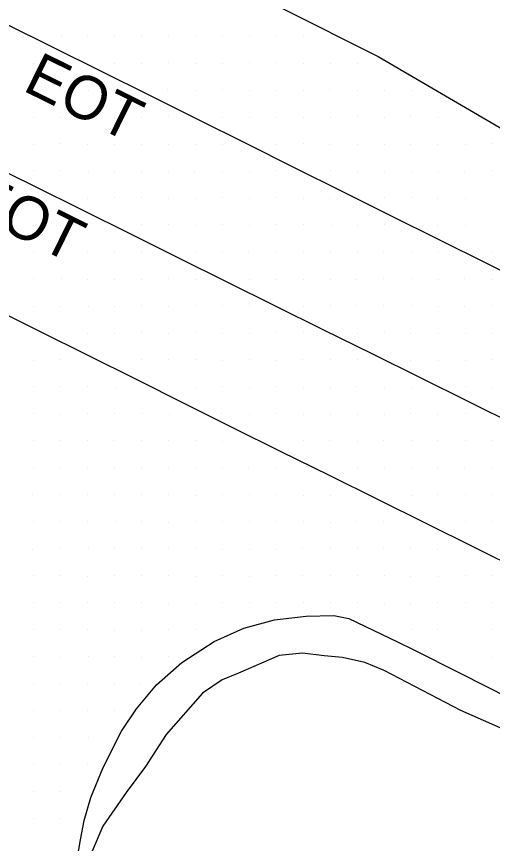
# Model space of a CAD drawing. Extents: x 2244337 to 2251208, y 199469 to 202984.
# Drawn here: x 2248960 to 2249004.1, y 200612.9 to 200689.5 of the extents above; entities that cross this region are included whole.
import ezdxf

# ---------------------------------------------------------------- set-up
doc = ezdxf.new("R2010")
doc.units = 0
for name, color, linetype in [('Exist DTM Scan Elevation Point', 7, 'Continuous'), ('Exist EOT Text', 7, 'Continuous'), ('Exist Roads EOP', 7, 'Continuous'), ('Exist Roads EOT', 7, 'Continuous')]:
    doc.layers.add(name, color=color, linetype=linetype)

msp = doc.modelspace()

# ---------------------------------------------------------------- linework, layer by layer
at = {"layer": 'Exist DTM Scan Elevation Point'}
for p, q in [((2248964.15, 200687.743), (2248964.15, 200687.743)), ((2248966.572, 200687.79), (2248966.572, 200687.79)), ((2248969.077, 200687.716), (2248969.077, 200687.716)), ((2248971.61, 200687.683), (2248971.61, 200687.683)), ((2248974.09, 200687.704), (2248974.09, 200687.704)), ((2248976.556, 200687.714), (2248976.556, 200687.714)), ((2248979.089, 200687.72), (2248979.089, 200687.72)), ((2248981.545, 200687.725), (2248981.545, 200687.725)), ((2248984.117, 200687.736), (2248984.117, 200687.736)), ((2248986.608, 200687.738), (2248986.608, 200687.738)), ((2248961.579, 200685.209), (2248961.579, 200685.209)), ((2248969.036, 200685.217), (2248969.036, 200685.217)), ((2248971.536, 200685.196), (2248971.536, 200685.196)), ((2248974.097, 200685.252), (2248974.097, 200685.252)), ((2248976.576, 200685.21), (2248976.576, 200685.21)), ((2248979.076, 200685.204), (2248979.076, 200685.204)), ((2248981.565, 200685.242), (2248981.565, 200685.242)), ((2248984.052, 200685.235), (2248984.052, 200685.235)), ((2248986.604, 200685.226), (2248986.604, 200685.226)), ((2248989.091, 200685.186), (2248989.091, 200685.186)), ((2248991.588, 200685.208), (2248991.588, 200685.208)), ((2248961.616, 200682.65), (2248961.616, 200682.65)), ((2248964.103, 200682.737), (2248964.103, 200682.737)), ((2248966.618, 200682.689), (2248966.618, 200682.689)), ((2248969.061, 200682.697), (2248969.061, 200682.697)), ((2248974.018, 200682.732), (2248974.018, 200682.732)), ((2248976.547, 200682.691), (2248976.547, 200682.691)), ((2248979.118, 200682.757), (2248979.118, 200682.757)), ((2248981.571, 200682.729), (2248981.571, 200682.729)), ((2248984.03, 200682.714), (2248984.03, 200682.714)), ((2248986.582, 200682.702), (2248986.582, 200682.702)), ((2248989.042, 200682.748), (2248989.042, 200682.748)), ((2248991.573, 200682.675), (2248991.573, 200682.675)), ((2248994.098, 200682.7), (2248994.098, 200682.7)), ((2248996.607, 200682.694), (2248996.607, 200682.694)), ((2248961.577, 200680.212), (2248961.577, 200680.212)), ((2248964.076, 200680.205), (2248964.076, 200680.205)), ((2248966.577, 200680.211), (2248966.577, 200680.211)), ((2248969.06, 200680.225), (2248969.06, 200680.225)), ((2248971.583, 200680.226), (2248971.583, 200680.226)), ((2248974.091, 200680.249), (2248974.091, 200680.249)), ((2248979.096, 200680.171), (2248979.096, 200680.171)), ((2248981.622, 200680.189), (2248981.622, 200680.189)), ((2248984.015, 200680.211), (2248984.015, 200680.211)), ((2248986.571, 200680.223), (2248986.571, 200680.223)), ((2248989.132, 200680.209), (2248989.132, 200680.209)), ((2248991.588, 200680.273), (2248991.588, 200680.273)), ((2248994.066, 200680.202), (2248994.066, 200680.202)), ((2248996.524, 200680.234), (2248996.524, 200680.234)), ((2248999.088, 200680.197), (2248999.088, 200680.197)), ((2248961.583, 200677.688), (2248961.583, 200677.688)), ((2248964.025, 200677.756), (2248964.025, 200677.756)), ((2248966.593, 200677.675), (2248966.593, 200677.675)), ((2248969.042, 200677.727), (2248969.042, 200677.727)), ((2248971.56, 200677.682), (2248971.56, 200677.682)), ((2248974.033, 200677.71), (2248974.033, 200677.71)), ((2248976.552, 200677.706), (2248976.552, 200677.706)), ((2248979.061, 200677.683), (2248979.061, 200677.683)), ((2248984.106, 200677.714), (2248984.106, 200677.714)), ((2248986.57, 200677.731), (2248986.57, 200677.731)), ((2248989.02, 200677.727), (2248989.02, 200677.727)), ((2248991.593, 200677.699), (2248991.593, 200677.699)), ((2248994.101, 200677.664), (2248994.101, 200677.664)), ((2248996.55, 200677.692), (2248996.55, 200677.692)), ((2248999.06, 200677.718), (2248999.06, 200677.718)), ((2249001.582, 200677.697), (2249001.582, 200677.697)), ((2249004.035, 200677.736), (2249004.035, 200677.736)), ((2248961.593, 200675.238), (2248961.593, 200675.238)), ((2248964.105, 200675.244), (2248964.105, 200675.244)), ((2248966.631, 200675.189), (2248966.631, 200675.189)), ((2248969.088, 200675.177), (2248969.088, 200675.177)), ((2248971.571, 200675.225), (2248971.571, 200675.225)), ((2248974.088, 200675.169), (2248974.088, 200675.169)), ((2248976.534, 200675.202), (2248976.534, 200675.202)), ((2248979.059, 200675.214), (2248979.059, 200675.214)), ((2248981.57, 200675.193), (2248981.57, 200675.193)), ((2248984.099, 200675.235), (2248984.099, 200675.235)), ((2248989.065, 200675.239), (2248989.065, 200675.239)), ((2248991.593, 200675.194), (2248991.593, 200675.194)), ((2248994.061, 200675.207), (2248994.061, 200675.207)), ((2248996.562, 200675.181), (2248996.562, 200675.181)), ((2248999.075, 200675.214), (2248999.075, 200675.214)), ((2249001.536, 200675.211), (2249001.536, 200675.211)), ((2249004.076, 200675.259), (2249004.076, 200675.259)), ((2248961.573, 200672.672), (2248961.573, 200672.672)), ((2248966.546, 200672.682), (2248966.546, 200672.682)), ((2248969.047, 200672.741), (2248969.047, 200672.741)), ((2248971.606, 200672.757), (2248971.606, 200672.757)), ((2248974.117, 200672.678), (2248974.117, 200672.678)), ((2248976.554, 200672.721), (2248976.554, 200672.721)), ((2248979.098, 200672.742), (2248979.098, 200672.742)), ((2248981.592, 200672.702), (2248981.592, 200672.702)), ((2248984.08, 200672.729), (2248984.08, 200672.729)), ((2248986.55, 200672.674), (2248986.55, 200672.674)), ((2248989.044, 200672.714), (2248989.044, 200672.714)), ((2248994.105, 200672.731), (2248994.105, 200672.731)), ((2248996.583, 200672.738), (2248996.583, 200672.738)), ((2248999.025, 200672.712), (2248999.025, 200672.712)), ((2249001.577, 200672.709), (2249001.577, 200672.709)), ((2248961.561, 200670.197), (2248961.561, 200670.197)), ((2248964.079, 200670.178), (2248964.079, 200670.178)), ((2248966.543, 200670.193), (2248966.543, 200670.193)), ((2248971.581, 200670.233), (2248971.581, 200670.233)), ((2248974.059, 200670.266), (2248974.059, 200670.266)), ((2248976.57, 200670.18), (2248976.57, 200670.18)), ((2248979.089, 200670.237), (2248979.089, 200670.237)), ((2248981.557, 200670.196), (2248981.557, 200670.196)), ((2248984.103, 200670.229), (2248984.103, 200670.229)), ((2248986.578, 200670.224), (2248986.578, 200670.224)), ((2248989.175, 200670.194), (2248989.175, 200670.194)), ((2248991.601, 200670.19), (2248991.601, 200670.19)), ((2248994.081, 200670.23), (2248994.081, 200670.23)), ((2248999.028, 200670.204), (2248999.028, 200670.204)), ((2249001.572, 200670.207), (2249001.572, 200670.207)), ((2248961.553, 200667.71), (2248961.553, 200667.71)), ((2248964.095, 200667.721), (2248964.095, 200667.721)), ((2248966.586, 200667.718), (2248966.586, 200667.718)), ((2248969.063, 200667.771), (2248969.063, 200667.771)), ((2248971.56, 200667.673), (2248971.56, 200667.673)), ((2248976.579, 200667.679), (2248976.579, 200667.679)), ((2248979.047, 200667.713), (2248979.047, 200667.713)), ((2248981.523, 200667.708), (2248981.523, 200667.708)), ((2248984.105, 200667.721), (2248984.105, 200667.721)), ((2248986.595, 200667.718), (2248986.595, 200667.718)), ((2248989.085, 200667.731), (2248989.085, 200667.731)), ((2248991.585, 200667.757), (2248991.585, 200667.757)), ((2248994.031, 200667.635), (2248994.031, 200667.635)), ((2248996.578, 200667.704), (2248996.578, 200667.704)), ((2248999.111, 200667.671), (2248999.111, 200667.671)), ((2249004.081, 200667.716), (2249004.081, 200667.716)), ((2248961.544, 200665.245), (2248961.544, 200665.245)), ((2248964.142, 200665.217), (2248964.142, 200665.217)), ((2248966.59, 200665.159), (2248966.59, 200665.159)), ((2248969.062, 200665.183), (2248969.062, 200665.183)), ((2248971.582, 200665.21), (2248971.582, 200665.21)), ((2248974.073, 200665.23), (2248974.073, 200665.23)), ((2248976.615, 200665.216), (2248976.615, 200665.216)), ((2248981.561, 200665.182), (2248981.561, 200665.182)), ((2248984.121, 200665.164), (2248984.121, 200665.164)), ((2248986.607, 200665.181), (2248986.607, 200665.181)), ((2248989.056, 200665.197), (2248989.056, 200665.197)), ((2248991.549, 200665.157), (2248991.549, 200665.157)), ((2248994, 200665.247), (2248994, 200665.247)), ((2248996.598, 200665.238), (2248996.598, 200665.238)), ((2248999.077, 200665.214), (2248999.077, 200665.214)), ((2249001.553, 200665.228), (2249001.553, 200665.228)), ((2249004.093, 200665.199), (2249004.093, 200665.199)), ((2248961.562, 200662.662), (2248961.562, 200662.662)), ((2248964.093, 200662.709), (2248964.093, 200662.709)), ((2248966.623, 200662.71), (2248966.623, 200662.71)), ((2248969.065, 200662.709), (2248969.065, 200662.709)), ((2248971.543, 200662.752), (2248971.543, 200662.752)), ((2248974.058, 200662.692), (2248974.058, 200662.692)), ((2248976.572, 200662.723), (2248976.572, 200662.723)), ((2248979.084, 200662.731), (2248979.084, 200662.731)), ((2248981.604, 200662.723), (2248981.604, 200662.723)), ((2248986.576, 200662.704), (2248986.576, 200662.704)), ((2248989.099, 200662.728), (2248989.099, 200662.728)), ((2248991.537, 200662.756), (2248991.537, 200662.756)), ((2248994.037, 200662.734), (2248994.037, 200662.734)), ((2248996.572, 200662.718), (2248996.572, 200662.718)), ((2248999.096, 200662.693), (2248999.096, 200662.693)), ((2249001.546, 200662.707), (2249001.546, 200662.707)), ((2249004.067, 200662.734), (2249004.067, 200662.734)), ((2248966.596, 200660.202), (2248966.596, 200660.202)), ((2248969.113, 200660.184), (2248969.113, 200660.184)), ((2248971.58, 200660.234), (2248971.58, 200660.234)), ((2248974.104, 200660.208), (2248974.104, 200660.208)), ((2248976.554, 200660.257), (2248976.554, 200660.257)), ((2248979.081, 200660.199), (2248979.081, 200660.199)), ((2248981.603, 200660.156), (2248981.603, 200660.156)), ((2248984.071, 200660.214), (2248984.071, 200660.214)), ((2248986.6, 200660.219), (2248986.6, 200660.219)), ((2248991.557, 200660.177), (2248991.557, 200660.177)), ((2248994.067, 200660.268), (2248994.067, 200660.268)), ((2248996.553, 200660.209), (2248996.553, 200660.209)), ((2248999.099, 200660.194), (2248999.099, 200660.194)), ((2249001.58, 200660.185), (2249001.58, 200660.185)), ((2249004.069, 200660.2), (2249004.069, 200660.2)), ((2248961.593, 200657.683), (2248961.593, 200657.683)), ((2248964.046, 200657.712), (2248964.046, 200657.712)), ((2248971.58, 200657.722), (2248971.58, 200657.722)), ((2248974.048, 200657.715), (2248974.048, 200657.715)), ((2248976.585, 200657.739), (2248976.585, 200657.739)), ((2248979.095, 200657.701), (2248979.095, 200657.701)), ((2248981.612, 200657.726), (2248981.612, 200657.726)), ((2248984.053, 200657.691), (2248984.053, 200657.691)), ((2248986.534, 200657.721), (2248986.534, 200657.721)), ((2248989.057, 200657.712), (2248989.057, 200657.712)), ((2248991.594, 200657.719), (2248991.594, 200657.719)), ((2248996.539, 200657.709), (2248996.539, 200657.709)), ((2248999.097, 200657.705), (2248999.097, 200657.705)), ((2249001.595, 200657.703), (2249001.595, 200657.703)), ((2249004.092, 200657.725), (2249004.092, 200657.725)), ((2248961.574, 200655.273), (2248961.574, 200655.273)), ((2248964.052, 200655.211), (2248964.052, 200655.211)), ((2248966.601, 200655.23), (2248966.601, 200655.23)), ((2248969.132, 200655.199), (2248969.132, 200655.199)), ((2248976.538, 200655.159), (2248976.538, 200655.159)), ((2248979.045, 200655.22), (2248979.045, 200655.22)), ((2248981.626, 200655.192), (2248981.626, 200655.192)), ((2248984.088, 200655.233), (2248984.088, 200655.233)), ((2248986.597, 200655.203), (2248986.597, 200655.203)), ((2248989.085, 200655.207), (2248989.085, 200655.207)), ((2248991.53, 200655.217), (2248991.53, 200655.217)), ((2248994.1, 200655.204), (2248994.1, 200655.204)), ((2248996.571, 200655.182), (2248996.571, 200655.182)), ((2249001.568, 200655.217), (2249001.568, 200655.217)), ((2249004.06, 200655.191), (2249004.06, 200655.191)), ((2248961.602, 200652.732), (2248961.602, 200652.732)), ((2248964.092, 200652.704), (2248964.092, 200652.704)), ((2248966.565, 200652.714), (2248966.565, 200652.714)), ((2248969.047, 200652.732), (2248969.047, 200652.732)), ((2248971.642, 200652.716), (2248971.642, 200652.716)), ((2248974.132, 200652.699), (2248974.132, 200652.699)), ((2248979.036, 200652.714), (2248979.036, 200652.714)), ((2248981.607, 200652.691), (2248981.607, 200652.691)), ((2248984.023, 200652.738), (2248984.023, 200652.738)), ((2248986.587, 200652.701), (2248986.587, 200652.701)), ((2248989.075, 200652.701), (2248989.075, 200652.701)), ((2248991.574, 200652.703), (2248991.574, 200652.703)), ((2248994.118, 200652.694), (2248994.118, 200652.694)), ((2248996.554, 200652.732), (2248996.554, 200652.732)), ((2248999.058, 200652.699), (2248999.058, 200652.699)), ((2249001.589, 200652.722), (2249001.589, 200652.722)), ((2248961.553, 200650.235), (2248961.553, 200650.235)), ((2248964.108, 200650.231), (2248964.108, 200650.231)), ((2248966.573, 200650.225), (2248966.573, 200650.225)), ((2248969.013, 200650.209), (2248969.013, 200650.209)), ((2248971.558, 200650.236), (2248971.558, 200650.236)), ((2248974.094, 200650.213), (2248974.094, 200650.213)), ((2248976.564, 200650.207), (2248976.564, 200650.207)), ((2248979.107, 200650.197), (2248979.107, 200650.197)), ((2248986.599, 200650.242), (2248986.599, 200650.242)), ((2248989.044, 200650.247), (2248989.044, 200650.247)), ((2248991.597, 200650.196), (2248991.597, 200650.196)), ((2248994.02, 200650.228), (2248994.02, 200650.228)), ((2248996.633, 200650.208), (2248996.633, 200650.208)), ((2248999.061, 200650.209), (2248999.061, 200650.209)), ((2249001.569, 200650.216), (2249001.569, 200650.216)), ((2249004.077, 200650.219), (2249004.077, 200650.219)), ((2248961.586, 200647.726), (2248961.586, 200647.726)), ((2248966.595, 200647.748), (2248966.595, 200647.748)), ((2248969.07, 200647.74), (2248969.07, 200647.74)), ((2248974.089, 200647.716), (2248974.089, 200647.716)), ((2248984.108, 200647.721), (2248984.108, 200647.721)), ((2248991.59, 200647.721), (2248991.59, 200647.721)), ((2248996.574, 200647.713), (2248996.574, 200647.713)), ((2249001.496, 200647.71), (2249001.496, 200647.71)), ((2248964.104, 200647.675), (2248964.104, 200647.675)), ((2248971.532, 200647.705), (2248971.532, 200647.705)), ((2248976.604, 200647.658), (2248976.604, 200647.658)), ((2248979.122, 200647.704), (2248979.122, 200647.704)), ((2248981.534, 200647.692), (2248981.534, 200647.692)), ((2248994.068, 200647.687), (2248994.068, 200647.687)), ((2248999.036, 200647.686), (2248999.036, 200647.686)), ((2249004.086, 200647.654), (2249004.086, 200647.654)), ((2248961.481, 200645.235), (2248961.481, 200645.235)), ((2248964.084, 200645.219), (2248964.084, 200645.219)), ((2248966.582, 200645.228), (2248966.582, 200645.228)), ((2248969.082, 200645.221), (2248969.082, 200645.221)), ((2248971.535, 200645.202), (2248971.535, 200645.202)), ((2248974.095, 200645.204), (2248974.095, 200645.204)), ((2248976.593, 200645.183), (2248976.593, 200645.183)), ((2248979.051, 200645.204), (2248979.051, 200645.204)), ((2248981.59, 200645.239), (2248981.59, 200645.239)), ((2248984.102, 200645.222), (2248984.102, 200645.222)), ((2248986.585, 200645.18), (2248986.585, 200645.18)), ((2248989.063, 200645.192), (2248989.063, 200645.192)), ((2248996.618, 200645.189), (2248996.618, 200645.189)), ((2248999.063, 200645.213), (2248999.063, 200645.213)), ((2249001.581, 200645.211), (2249001.581, 200645.211)), ((2249004.058, 200645.221), (2249004.058, 200645.221)), ((2248961.562, 200642.73), (2248961.562, 200642.73)), ((2248964.051, 200642.71), (2248964.051, 200642.71)), ((2248966.607, 200642.706), (2248966.607, 200642.706)), ((2248969.122, 200642.713), (2248969.122, 200642.713)), ((2248971.621, 200642.71), (2248971.621, 200642.71)), ((2248974.062, 200642.697), (2248974.062, 200642.697)), ((2248976.604, 200642.725), (2248976.604, 200642.725)), ((2248979.043, 200642.723), (2248979.043, 200642.723)), ((2248981.579, 200642.758), (2248981.579, 200642.758)), ((2248984.063, 200642.721), (2248984.063, 200642.721)), ((2248986.574, 200642.721), (2248986.574, 200642.721)), ((2248989.085, 200642.656), (2248989.085, 200642.656)), ((2248991.548, 200642.707), (2248991.548, 200642.707)), ((2248994.034, 200642.73), (2248994.034, 200642.73)), ((2249001.568, 200642.762), (2249001.568, 200642.762)), ((2249004.075, 200642.707), (2249004.075, 200642.707)), ((2248961.501, 200640.178), (2248961.501, 200640.178)), ((2248964.027, 200640.2), (2248964.027, 200640.2)), ((2248966.622, 200640.202), (2248966.622, 200640.202)), ((2248969.075, 200640.202), (2248969.075, 200640.202)), ((2248971.569, 200640.241), (2248971.569, 200640.241)), ((2248974.069, 200640.218), (2248974.069, 200640.218)), ((2248976.606, 200640.205), (2248976.606, 200640.205)), ((2248979.057, 200640.186), (2248979.057, 200640.186)), ((2248981.596, 200640.186), (2248981.596, 200640.186)), ((2248984.01, 200640.193), (2248984.01, 200640.193)), ((2248986.539, 200640.197), (2248986.539, 200640.197)), ((2248989.073, 200640.205), (2248989.073, 200640.205)), ((2248991.618, 200640.199), (2248991.618, 200640.199)), ((2248994.043, 200640.232), (2248994.043, 200640.232)), ((2248996.527, 200640.22), (2248996.527, 200640.22)), ((2248999.048, 200640.192), (2248999.048, 200640.192)), ((2248971.57, 200637.781), (2248971.57, 200637.781)), ((2248961.544, 200637.721), (2248961.544, 200637.721)), ((2248964.068, 200637.73), (2248964.068, 200637.73)), ((2248966.575, 200637.679), (2248966.575, 200637.679)), ((2248969.069, 200637.726), (2248969.069, 200637.726)), ((2248974.079, 200637.698), (2248974.079, 200637.698)), ((2248976.598, 200637.694), (2248976.598, 200637.694)), ((2248979.059, 200637.722), (2248979.059, 200637.722)), ((2248981.586, 200637.678), (2248981.586, 200637.678)), ((2248984.079, 200637.702), (2248984.079, 200637.702)), ((2248986.537, 200637.718), (2248986.537, 200637.718)), ((2248989.122, 200637.715), (2248989.122, 200637.715)), ((2248991.616, 200637.714), (2248991.616, 200637.714)), ((2248994.084, 200637.712), (2248994.084, 200637.712)), ((2248996.558, 200637.694), (2248996.558, 200637.694)), ((2248999.098, 200637.691), (2248999.098, 200637.691)), ((2249001.598, 200637.713), (2249001.598, 200637.713)), ((2249004.074, 200637.729), (2249004.074, 200637.729)), ((2248961.562, 200635.221), (2248961.562, 200635.221)), ((2248964.097, 200635.231), (2248964.097, 200635.231)), ((2248966.59, 200635.213), (2248966.59, 200635.213)), ((2248969.104, 200635.214), (2248969.104, 200635.214)), ((2248971.541, 200635.197), (2248971.541, 200635.197)), ((2248974.052, 200635.168), (2248974.052, 200635.168)), ((2248976.544, 200635.155), (2248976.544, 200635.155)), ((2248979.087, 200635.209), (2248979.087, 200635.209)), ((2248981.611, 200635.2), (2248981.611, 200635.2)), ((2248984.089, 200635.234), (2248984.089, 200635.234)), ((2248986.557, 200635.264), (2248986.557, 200635.264)), ((2248989.054, 200635.274), (2248989.054, 200635.274)), ((2248991.631, 200635.243), (2248991.631, 200635.243)), ((2248994.078, 200635.187), (2248994.078, 200635.187)), ((2248996.524, 200635.185), (2248996.524, 200635.185)), ((2248999.058, 200635.205), (2248999.058, 200635.205)), ((2249001.64, 200635.234), (2249001.64, 200635.234)), ((2249004.037, 200635.227), (2249004.037, 200635.227)), ((2248961.573, 200632.77), (2248961.573, 200632.77)), ((2248964.092, 200632.693), (2248964.092, 200632.693)), ((2248966.562, 200632.706), (2248966.562, 200632.706)), ((2248969.082, 200632.678), (2248969.082, 200632.678)), ((2248971.614, 200632.684), (2248971.614, 200632.684)), ((2248974.068, 200632.714), (2248974.068, 200632.714)), ((2248976.581, 200632.719), (2248976.581, 200632.719)), ((2248996.58, 200632.713), (2248996.58, 200632.713)), ((2248999.048, 200632.73), (2248999.048, 200632.73)), ((2249004.075, 200632.747), (2249004.075, 200632.747)), ((2248961.553, 200630.223), (2248961.553, 200630.223)), ((2248964.084, 200630.167), (2248964.084, 200630.167)), ((2248966.633, 200630.195), (2248966.633, 200630.195)), ((2248969.047, 200630.206), (2248969.047, 200630.206)), ((2248971.558, 200630.174), (2248971.558, 200630.174)), ((2248974.077, 200630.223), (2248974.077, 200630.223)), ((2249004.056, 200630.172), (2249004.056, 200630.172)), ((2248961.542, 200627.756), (2248961.542, 200627.756)), ((2248964.095, 200627.722), (2248964.095, 200627.722)), ((2248966.571, 200627.714), (2248966.571, 200627.714)), ((2248969.065, 200627.722), (2248969.065, 200627.722)), ((2248971.523, 200627.725), (2248971.523, 200627.725)), ((2248961.561, 200625.233), (2248961.561, 200625.233)), ((2248964.111, 200625.213), (2248964.111, 200625.213)), ((2248966.594, 200625.228), (2248966.594, 200625.228)), ((2248969.061, 200625.205), (2248969.061, 200625.205)), ((2248961.562, 200622.743), (2248961.562, 200622.743)), ((2248964.069, 200622.7), (2248964.069, 200622.7)), ((2248966.615, 200622.732), (2248966.615, 200622.732)), ((2248961.559, 200620.195), (2248961.559, 200620.195)), ((2248964.056, 200620.253), (2248964.056, 200620.253)), ((2248966.586, 200620.216), (2248966.586, 200620.216)), ((2248961.599, 200617.694), (2248961.599, 200617.694)), ((2248964.065, 200617.747), (2248964.065, 200617.747)), ((2248961.591, 200615.219), (2248961.591, 200615.219)), ((2248964.084, 200615.235), (2248964.084, 200615.235))]:
    msp.add_line(p, q, dxfattribs=at)
at = {"layer": 'Exist Roads EOP'}
for points in [[(2248886.354, 200739.931), (2248913.078, 200726.305), (2248939.882, 200712.863), (2248966.655, 200699.338), (2248993.504, 200685.83), (2249004.721, 200679.3), (2249005.573, 200678.51), (2249005.961, 200677.39), (2249005.014, 200670.366), (2249009.548, 200668.255), (2249014.027, 200666.031), (2249040.846, 200652.597), (2249067.756, 200639.328), (2249094.546, 200625.819), (2249121.53, 200612.727), (2249148.203, 200598.994), (2249175.342, 200586.2), (2249202.079, 200572.571)], [(2249037.645, 200608.568), (2249010.356, 200621.17), (2249001.168, 200625.236), (2248994.08, 200628.949), (2248992.271, 200629.672), (2248990.197, 200630.137), (2248988.504, 200630.31), (2248986.514, 200630.533), (2248984.346, 200630.316), (2248980.569, 200628.678), (2248979.055, 200628.058), (2248977.238, 200626.823), (2248973.868, 200622.993), (2248971.954, 200620.051), (2248970.164, 200617.627), (2248967.987, 200614.504), (2248966.915, 200611.977)]]:
    msp.add_lwpolyline(points, dxfattribs=at)
at = {"layer": 'Exist Roads EOT'}
for points in [[(2248958.859, 200688.91), (2248963.342, 200686.696), (2248967.825, 200684.481), (2248972.303, 200682.256), (2248976.78, 200680.032), (2248981.254, 200677.798), (2248985.727, 200675.564), (2248990.2, 200673.33), (2248994.673, 200671.096), (2248999.149, 200668.867), (2249003.625, 200666.638), (2249008.103, 200664.414), (2249012.581, 200662.19), (2249017.059, 200659.965), (2249021.537, 200657.741), (2249026.016, 200655.52), (2249030.496, 200653.298), (2249034.976, 200651.079), (2249039.456, 200648.859), (2249043.937, 200646.64), (2249048.417, 200644.421)], [(2248957.1, 200676.057), (2248961.579, 200673.835), (2248966.059, 200671.615), (2248970.54, 200669.395), (2248975.02, 200667.176), (2248979.501, 200664.957), (2248983.982, 200662.739), (2248988.462, 200660.52), (2248992.943, 200658.301), (2248997.424, 200656.082), (2249001.904, 200653.863), (2249006.385, 200651.644), (2249010.865, 200649.424), (2249015.346, 200647.205), (2249019.826, 200644.986), (2249024.307, 200642.766), (2249028.787, 200640.546), (2249033.267, 200638.327), (2249037.747, 200636.107), (2249042.228, 200633.887), (2249046.708, 200631.667), (2249051.188, 200629.447)], [(2248957.639, 200662.597), (2248962.117, 200660.373), (2248966.595, 200658.15), (2248971.071, 200655.921), (2248975.547, 200653.693), (2248980.024, 200651.467), (2248984.501, 200649.241), (2248988.983, 200647.023), (2248993.464, 200644.806), (2248997.946, 200642.589), (2249002.427, 200640.371), (2249006.909, 200638.155), (2249011.391, 200635.939), (2249015.875, 200633.726), (2249020.358, 200631.512), (2249024.841, 200629.299), (2249029.325, 200627.086), (2249033.808, 200624.872), (2249038.292, 200622.659), (2249042.775, 200620.445), (2249047.258, 200618.231), (2249051.741, 200616.018)], [(2248965.332, 200609.856), (2248965.914, 200613.237), (2248966.26, 200615.027), (2248966.89, 200617.179), (2248968.013, 200619.935), (2248969.72, 200623.306), (2248971.118, 200625.375), (2248972.962, 200627.617), (2248975.328, 200629.679), (2248978.324, 200631.627), (2248981.059, 200632.858), (2248983.921, 200633.624), (2248986.833, 200633.974), (2248989.396, 200634.041), (2248990.807, 200633.751), (2248995.311, 200631.58), (2248996.714, 200630.904)], [(2248996.714, 200630.904), (2249001.176, 200628.647), (2249005.685, 200626.365), (2249010.177, 200624.168), (2249013.789, 200622.402), (2249018.243, 200620.128), (2249018.948, 200619.768), (2249023.436, 200617.566), (2249024.32, 200617.133), (2249028.802, 200614.915), (2249033.298, 200612.691), (2249037.848, 200610.618), (2249040.72, 200609.311), (2249045.277, 200607.253), (2249047.097, 200606.431), (2249051.717, 200604.519)]]:
    msp.add_lwpolyline(points, dxfattribs=at)

# ---------------------------------------------------------------- texts
at = {"layer": 'Exist EOT Text'}
for rotation, p in [(333.70926, (2248960.454, 200682.737)), (333.62266, (2248955.041, 200671.574))]:
    msp.add_text('EOT', height=4.02, rotation=rotation, dxfattribs=at).set_placement(p)

doc.saveas('drawing.dxf')
